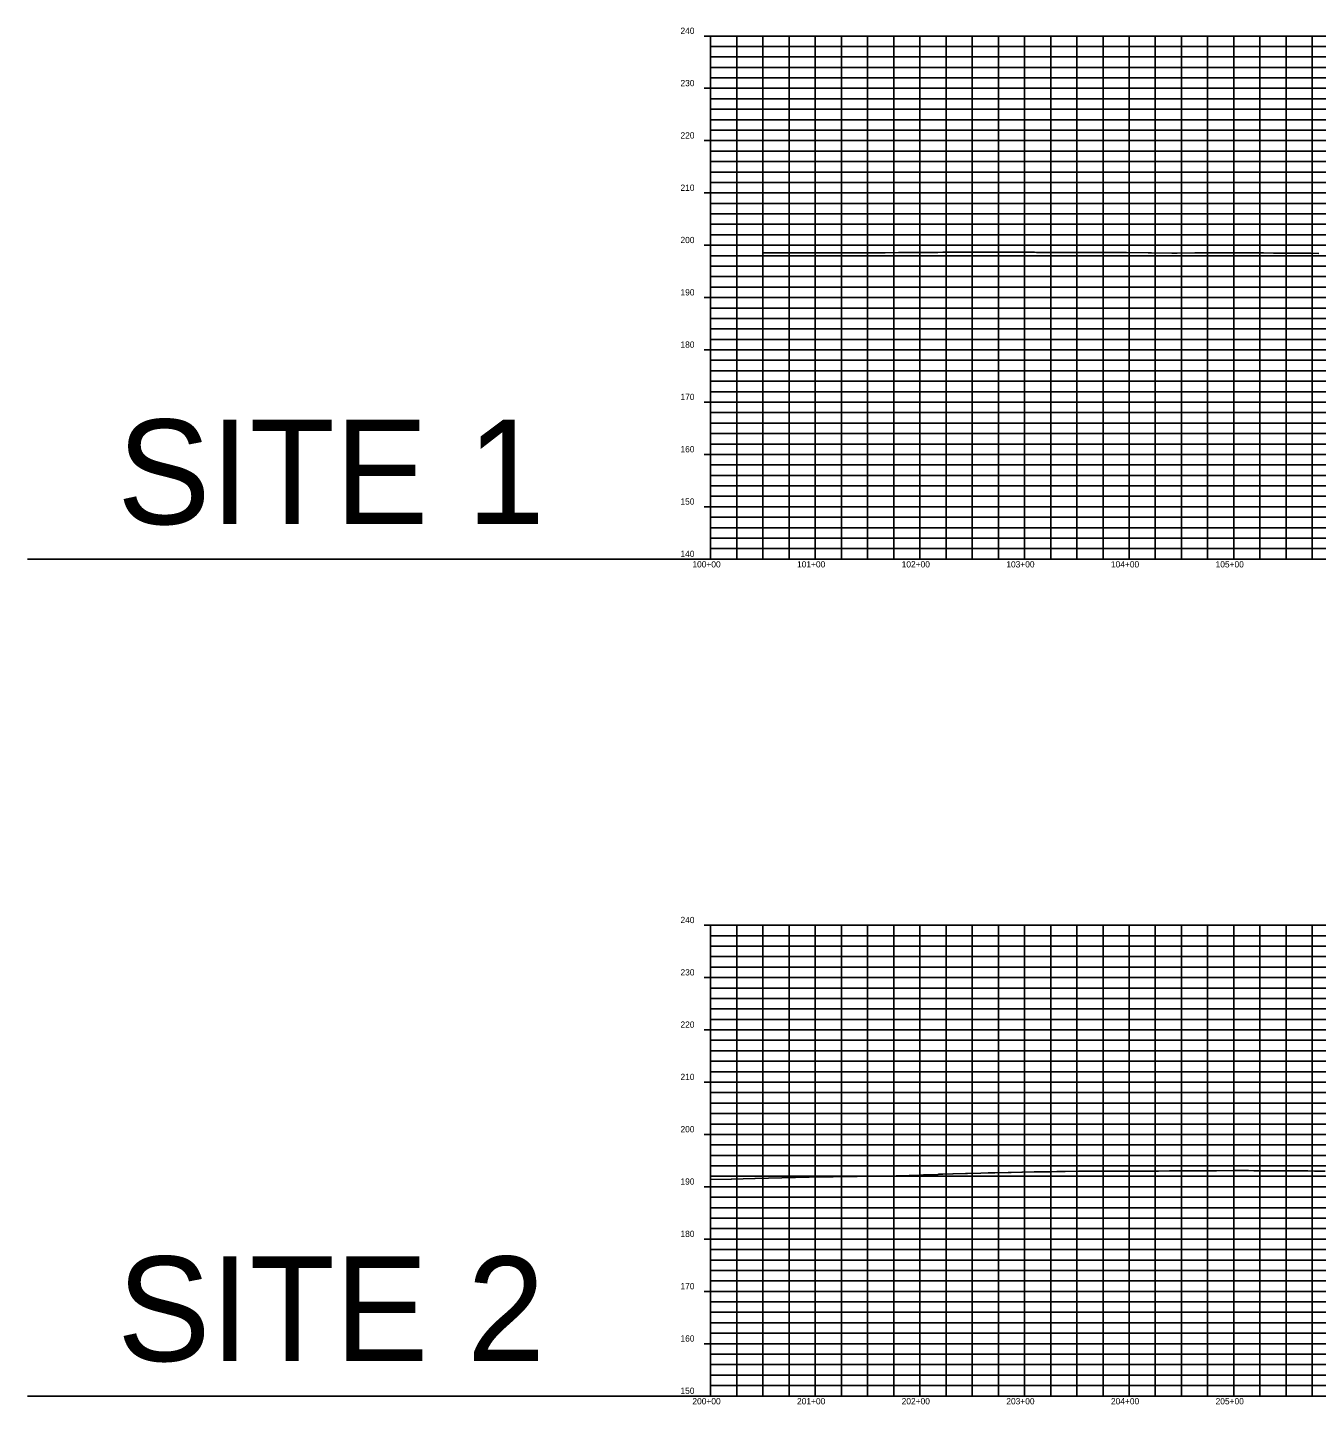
# Model space of a CAD drawing. Extents: x 1399671 to 1408349, y 1930471 to 1933387.
# Drawn here: x 1399671 to 1400903, y 1932071 to 1933387 of the extents above; entities that cross this region are included whole.
import ezdxf

# ---------------------------------------------------------------- set-up
doc = ezdxf.new("R2010")
doc.units = 0
for name, color, linetype in [('63', 7, 'Continuous'), ('8', 7, 'Continuous'), ('R_Exist Surface', 7, 'Continuous'), ('R_Grid', 7, 'Continuous'), ('R_Grid Annot', 7, 'Continuous')]:
    doc.layers.add(name, color=color, linetype=linetype)

msp = doc.modelspace()

# ---------------------------------------------------------------- linework, layer by layer
at = {"layer": '8'}
for p, q in [((1400324.2, 1932878.6), (1399671.4, 1932878.6)), ((1400324.2, 1932078.6), (1399671.4, 1932078.6))]:
    msp.add_line(p, q, dxfattribs=at)
at = {"layer": 'R_Exist Surface'}
for points in [[(1400374.2, 1933171.3), (1400384.1, 1933171.3), (1400384.1, 1933171.3), (1400388.6, 1933171.4), (1400397, 1933171.4), (1400397.1, 1933171.4), (1400414, 1933171.4), (1400414, 1933171.4), (1400414, 1933171.4), (1400431, 1933171.4), (1400431, 1933171.4), (1400447.9, 1933171.4), (1400447.9, 1933171.4), (1400464.9, 1933171.4), (1400464.9, 1933171.4), (1400477.9, 1933171.5), (1400477.9, 1933171.5), (1400480.9, 1933171.5), (1400490.9, 1933171.5), (1400490.9, 1933171.5), (1400503.9, 1933171.6), (1400503.9, 1933171.6), (1400516.9, 1933171.6), (1400524.2, 1933171.7), (1400541, 1933171.8), (1400541.3, 1933171.8), (1400546.1, 1933171.9), (1400565.4, 1933172), (1400565.6, 1933172), (1400568, 1933172), (1400578.5, 1933172), (1400578.5, 1933172), (1400584.6, 1933172), (1400589.9, 1933172), (1400591.3, 1933172), (1400591.4, 1933172), (1400591.4, 1933172), (1400604.3, 1933172), (1400604.4, 1933172), (1400611.7, 1933172), (1400617.1, 1933172), (1400617.6, 1933172), (1400633.6, 1933171.9), (1400635.7, 1933171.8), (1400653.6, 1933171.7), (1400654.3, 1933171.7), (1400655.5, 1933171.7), (1400669.7, 1933171.7), (1400670.6, 1933171.7), (1400677.4, 1933171.7), (1400685.7, 1933171.7), (1400686.8, 1933171.7), (1400699.3, 1933171.7), (1400701.6, 1933171.7), (1400703, 1933171.7), (1400704.3, 1933171.7), (1400719.2, 1933171.7), (1400721.2, 1933171.6), (1400721.6, 1933171.6), (1400742.4, 1933171.4), (1400743.1, 1933171.4), (1400745.6, 1933171.4), (1400765, 1933171.1), (1400765.7, 1933171.1), (1400770, 1933171.1), (1400786.9, 1933171.2), (1400790.2, 1933171.2), (1400795.6, 1933171.3), (1400808.7, 1933171.3), (1400814.8, 1933171.3), (1400826.2, 1933171.3), (1400830.6, 1933171.3), (1400830.6, 1933171.3), (1400835.3, 1933171.3), (1400846.4, 1933171.2), (1400851.6, 1933171.2), (1400852.5, 1933171.2), (1400862.2, 1933171.1), (1400868.1, 1933171.1), (1400874.4, 1933171.1), (1400878, 1933171.1), (1400883.6, 1933171), (1400891.7, 1933171), (1400896.3, 1933170.9), (1400897.9, 1933170.9), (1400905.4, 1933170.8)], [(1400324.2, 1932285.4), (1400343.9, 1932286), (1400344.1, 1932286), (1400366.4, 1932286.6), (1400366.7, 1932286.6), (1400379.4, 1932286.9), (1400379.6, 1932286.9), (1400392.3, 1932287.2), (1400392.4, 1932287.2), (1400405.2, 1932287.5), (1400405.3, 1932287.5), (1400418.2, 1932287.8), (1400418.2, 1932287.8), (1400418.3, 1932287.8), (1400441.1, 1932288.1), (1400441.3, 1932288.1), (1400463.9, 1932288.3), (1400464.1, 1932288.3), (1400476.5, 1932288.6), (1400476.7, 1932288.6), (1400489, 1932288.9), (1400489.3, 1932288.9), (1400501.6, 1932289.2), (1400513.9, 1932289.5), (1400514.2, 1932289.5), (1400524.2, 1932289.8), (1400527.6, 1932290), (1400528, 1932290), (1400541.4, 1932290.4), (1400541.8, 1932290.4), (1400542.1, 1932290.5), (1400546, 1932290.6), (1400555.6, 1932290.9), (1400555.9, 1932290.9), (1400567.8, 1932291.4), (1400569.4, 1932291.4), (1400569.7, 1932291.4), (1400582.5, 1932291.7), (1400589.6, 1932291.9), (1400595.4, 1932292), (1400595.7, 1932292), (1400608.7, 1932292.3), (1400608.8, 1932292.3), (1400611.4, 1932292.4), (1400621.9, 1932292.6), (1400621.9, 1932292.6), (1400622.2, 1932292.6), (1400633.3, 1932292.8), (1400635.6, 1932292.8), (1400635.7, 1932292.8), (1400649.2, 1932293), (1400655.1, 1932293.1), (1400662.3, 1932293.2), (1400662.9, 1932293.2), (1400675.8, 1932293.4), (1400676.6, 1932293.4), (1400676.9, 1932293.4), (1400698.5, 1932293.5), (1400698.7, 1932293.5), (1400700.6, 1932293.5), (1400702.8, 1932293.5), (1400720.5, 1932293.5), (1400724.6, 1932293.5), (1400726.3, 1932293.5), (1400737.3, 1932293.6), (1400739.2, 1932293.6), (1400742.3, 1932293.6), (1400750, 1932293.6), (1400752.2, 1932293.6), (1400762.8, 1932293.7), (1400764.1, 1932293.7), (1400772.9, 1932293.7), (1400775.5, 1932293.7), (1400786, 1932293.8), (1400794.3, 1932293.9), (1400800.2, 1932293.9), (1400806.6, 1932294), (1400807.8, 1932294), (1400824.7, 1932294.1), (1400829.1, 1932294.1), (1400829.6, 1932294.1), (1400838.3, 1932294.1), (1400843.2, 1932294), (1400851.4, 1932294), (1400851.8, 1932294), (1400859.9, 1932294), (1400865.4, 1932294), (1400873, 1932294), (1400873.2, 1932294), (1400879, 1932293.9), (1400890.6, 1932293.7), (1400895, 1932293.7), (1400901.4, 1932293.6), (1400911.5, 1932293.4)]]:
    msp.add_lwpolyline(points, dxfattribs=at)
at = {"layer": 'R_Grid'}
for p, q in [((1400324.2, 1932878.6), (1400324.2, 1933378.6)), ((1400324.2, 1933378.6), (1408224.2, 1933378.6)), ((1400324.2, 1933378.6), (1408224.2, 1933378.6)), ((1400324.2, 1933368.6), (1408224.2, 1933368.6)), ((1400349.2, 1932878.6), (1400349.2, 1933378.6)), ((1400374.2, 1932878.6), (1400374.2, 1933378.6)), ((1400399.2, 1932878.6), (1400399.2, 1933378.6)), ((1400424.2, 1932878.6), (1400424.2, 1933378.6)), ((1400449.2, 1932878.6), (1400449.2, 1933378.6)), ((1400474.2, 1932878.6), (1400474.2, 1933378.6)), ((1400499.2, 1932878.6), (1400499.2, 1933378.6)), ((1400524.2, 1932878.6), (1400524.2, 1933378.6)), ((1400549.2, 1932878.6), (1400549.2, 1933378.6)), ((1400574.2, 1932878.6), (1400574.2, 1933378.6)), ((1400599.2, 1932878.6), (1400599.2, 1933378.6)), ((1400624.2, 1932878.6), (1400624.2, 1933378.6)), ((1400649.2, 1932878.6), (1400649.2, 1933378.6)), ((1400674.2, 1932878.6), (1400674.2, 1933378.6)), ((1400699.2, 1932878.6), (1400699.2, 1933378.6)), ((1400724.2, 1932878.6), (1400724.2, 1933378.6)), ((1400749.2, 1932878.6), (1400749.2, 1933378.6)), ((1400774.2, 1932878.6), (1400774.2, 1933378.6)), ((1400799.2, 1932878.6), (1400799.2, 1933378.6)), ((1400824.2, 1932878.6), (1400824.2, 1933378.6)), ((1400849.2, 1932878.6), (1400849.2, 1933378.6)), ((1400874.2, 1932878.6), (1400874.2, 1933378.6)), ((1400899.2, 1932878.6), (1400899.2, 1933378.6)), ((1400324.2, 1933358.6), (1408224.2, 1933358.6)), ((1400324.2, 1933348.6), (1408224.2, 1933348.6)), ((1400324.2, 1933338.6), (1408224.2, 1933338.6)), ((1400324.2, 1933328.6), (1408224.2, 1933328.6)), ((1400324.2, 1933318.6), (1408224.2, 1933318.6)), ((1400324.2, 1933308.6), (1408224.2, 1933308.6)), ((1400324.2, 1933298.6), (1408224.2, 1933298.6)), ((1400324.2, 1933288.6), (1408224.2, 1933288.6)), ((1400324.2, 1933278.6), (1408224.2, 1933278.6)), ((1400324.2, 1933268.6), (1408224.2, 1933268.6)), ((1400324.2, 1933258.6), (1408224.2, 1933258.6)), ((1400324.2, 1933248.6), (1408224.2, 1933248.6)), ((1400324.2, 1933238.6), (1408224.2, 1933238.6)), ((1400324.2, 1933228.6), (1408224.2, 1933228.6)), ((1400324.2, 1933218.6), (1408224.2, 1933218.6)), ((1400324.2, 1933208.6), (1408224.2, 1933208.6)), ((1400324.2, 1933198.6), (1408224.2, 1933198.6)), ((1400324.2, 1933188.6), (1408224.2, 1933188.6)), ((1400324.2, 1933178.6), (1408224.2, 1933178.6)), ((1400324.2, 1933168.6), (1408224.2, 1933168.6)), ((1400324.2, 1933158.6), (1408224.2, 1933158.6)), ((1400324.2, 1933148.6), (1408224.2, 1933148.6)), ((1400324.2, 1933138.6), (1408224.2, 1933138.6)), ((1400324.2, 1933128.6), (1408224.2, 1933128.6)), ((1400324.2, 1933118.6), (1408224.2, 1933118.6)), ((1400324.2, 1933108.6), (1408224.2, 1933108.6)), ((1400324.2, 1933098.6), (1408224.2, 1933098.6)), ((1400324.2, 1933088.6), (1408224.2, 1933088.6)), ((1400324.2, 1933078.6), (1408224.2, 1933078.6)), ((1400324.2, 1933068.6), (1408224.2, 1933068.6)), ((1400324.2, 1933058.6), (1408224.2, 1933058.6)), ((1400324.2, 1933048.6), (1408224.2, 1933048.6)), ((1400324.2, 1933038.6), (1408224.2, 1933038.6)), ((1400324.2, 1933028.6), (1408224.2, 1933028.6)), ((1400324.2, 1933018.6), (1408224.2, 1933018.6)), ((1400324.2, 1933008.6), (1408224.2, 1933008.6)), ((1400324.2, 1932998.6), (1408224.2, 1932998.6)), ((1400324.2, 1932988.6), (1408224.2, 1932988.6)), ((1400324.2, 1932978.6), (1408224.2, 1932978.6)), ((1400324.2, 1932968.6), (1408224.2, 1932968.6)), ((1400324.2, 1932958.6), (1408224.2, 1932958.6)), ((1400324.2, 1932948.6), (1408224.2, 1932948.6)), ((1400324.2, 1932938.6), (1408224.2, 1932938.6)), ((1400324.2, 1932928.6), (1408224.2, 1932928.6)), ((1400324.2, 1932918.6), (1408224.2, 1932918.6)), ((1400324.2, 1932908.6), (1408224.2, 1932908.6)), ((1400324.2, 1932898.6), (1408224.2, 1932898.6)), ((1400324.2, 1932888.6), (1408224.2, 1932888.6)), ((1400324.2, 1932878.6), (1408224.2, 1932878.6)), ((1400324.2, 1932078.6), (1400324.2, 1932528.6)), ((1400324.2, 1932528.6), (1407124.2, 1932528.6)), ((1400324.2, 1932528.6), (1407124.2, 1932528.6)), ((1400349.2, 1932078.6), (1400349.2, 1932528.6)), ((1400374.2, 1932078.6), (1400374.2, 1932528.6)), ((1400399.2, 1932078.6), (1400399.2, 1932528.6)), ((1400424.2, 1932078.6), (1400424.2, 1932528.6)), ((1400449.2, 1932078.6), (1400449.2, 1932528.6)), ((1400474.2, 1932078.6), (1400474.2, 1932528.6)), ((1400499.2, 1932078.6), (1400499.2, 1932528.6)), ((1400524.2, 1932078.6), (1400524.2, 1932528.6)), ((1400549.2, 1932078.6), (1400549.2, 1932528.6)), ((1400574.2, 1932078.6), (1400574.2, 1932528.6)), ((1400599.2, 1932078.6), (1400599.2, 1932528.6)), ((1400624.2, 1932078.6), (1400624.2, 1932528.6)), ((1400649.2, 1932078.6), (1400649.2, 1932528.6)), ((1400674.2, 1932078.6), (1400674.2, 1932528.6)), ((1400699.2, 1932078.6), (1400699.2, 1932528.6)), ((1400724.2, 1932078.6), (1400724.2, 1932528.6)), ((1400749.2, 1932078.6), (1400749.2, 1932528.6)), ((1400774.2, 1932078.6), (1400774.2, 1932528.6)), ((1400799.2, 1932078.6), (1400799.2, 1932528.6)), ((1400824.2, 1932078.6), (1400824.2, 1932528.6)), ((1400849.2, 1932078.6), (1400849.2, 1932528.6)), ((1400874.2, 1932078.6), (1400874.2, 1932528.6)), ((1400899.2, 1932078.6), (1400899.2, 1932528.6)), ((1400324.2, 1932518.6), (1407124.2, 1932518.6)), ((1400324.2, 1932508.6), (1407124.2, 1932508.6)), ((1400324.2, 1932498.6), (1407124.2, 1932498.6)), ((1400324.2, 1932488.6), (1407124.2, 1932488.6)), ((1400324.2, 1932478.6), (1407124.2, 1932478.6)), ((1400324.2, 1932468.6), (1407124.2, 1932468.6)), ((1400324.2, 1932458.6), (1407124.2, 1932458.6)), ((1400324.2, 1932448.6), (1407124.2, 1932448.6)), ((1400324.2, 1932438.6), (1407124.2, 1932438.6)), ((1400324.2, 1932428.6), (1407124.2, 1932428.6)), ((1400324.2, 1932418.6), (1407124.2, 1932418.6)), ((1400324.2, 1932408.6), (1407124.2, 1932408.6)), ((1400324.2, 1932398.6), (1407124.2, 1932398.6)), ((1400324.2, 1932388.6), (1407124.2, 1932388.6)), ((1400324.2, 1932378.6), (1407124.2, 1932378.6)), ((1400324.2, 1932368.6), (1407124.2, 1932368.6)), ((1400324.2, 1932358.6), (1407124.2, 1932358.6)), ((1400324.2, 1932348.6), (1407124.2, 1932348.6)), ((1400324.2, 1932338.6), (1407124.2, 1932338.6)), ((1400324.2, 1932328.6), (1407124.2, 1932328.6)), ((1400324.2, 1932318.6), (1407124.2, 1932318.6)), ((1400324.2, 1932308.6), (1407124.2, 1932308.6)), ((1400324.2, 1932298.6), (1407124.2, 1932298.6)), ((1400324.2, 1932288.6), (1407124.2, 1932288.6)), ((1400324.2, 1932278.6), (1407124.2, 1932278.6)), ((1400324.2, 1932268.6), (1407124.2, 1932268.6)), ((1400324.2, 1932258.6), (1407124.2, 1932258.6)), ((1400324.2, 1932248.6), (1407124.2, 1932248.6)), ((1400324.2, 1932238.6), (1407124.2, 1932238.6)), ((1400324.2, 1932228.6), (1407124.2, 1932228.6)), ((1400324.2, 1932218.6), (1407124.2, 1932218.6)), ((1400324.2, 1932208.6), (1407124.2, 1932208.6)), ((1400324.2, 1932198.6), (1407124.2, 1932198.6)), ((1400324.2, 1932188.6), (1407124.2, 1932188.6)), ((1400324.2, 1932178.6), (1407124.2, 1932178.6)), ((1400324.2, 1932168.6), (1407124.2, 1932168.6)), ((1400324.2, 1932158.6), (1407124.2, 1932158.6)), ((1400324.2, 1932148.6), (1407124.2, 1932148.6)), ((1400324.2, 1932138.6), (1407124.2, 1932138.6)), ((1400324.2, 1932128.6), (1407124.2, 1932128.6)), ((1400324.2, 1932118.6), (1407124.2, 1932118.6)), ((1400324.2, 1932108.6), (1407124.2, 1932108.6)), ((1400324.2, 1932098.6), (1407124.2, 1932098.6)), ((1400324.2, 1932088.6), (1407124.2, 1932088.6)), ((1400324.2, 1932078.6), (1407124.2, 1932078.6))]:
    msp.add_line(p, q, dxfattribs=at)
at = {"layer": 'R_Grid Annot'}
for p, q in [((1400318.2, 1933378.6), (1400324.2, 1933378.6)), ((1400318.2, 1933378.6), (1400324.2, 1933378.6)), ((1400324.2, 1933368.6), (1400327.2, 1933368.6)), ((1400324.2, 1933358.6), (1400327.2, 1933358.6)), ((1400324.2, 1933348.6), (1400327.2, 1933348.6)), ((1400324.2, 1933338.6), (1400327.2, 1933338.6)), ((1400318.2, 1933328.6), (1400324.2, 1933328.6)), ((1400324.2, 1933318.6), (1400327.2, 1933318.6)), ((1400324.2, 1933308.6), (1400327.2, 1933308.6)), ((1400324.2, 1933298.6), (1400327.2, 1933298.6)), ((1400318.2, 1933278.6), (1400324.2, 1933278.6)), ((1400324.2, 1933288.6), (1400327.2, 1933288.6)), ((1400324.2, 1933268.6), (1400327.2, 1933268.6)), ((1400324.2, 1933258.6), (1400327.2, 1933258.6)), ((1400324.2, 1933248.6), (1400327.2, 1933248.6)), ((1400324.2, 1933238.6), (1400327.2, 1933238.6)), ((1400318.2, 1933228.6), (1400324.2, 1933228.6)), ((1400324.2, 1933218.6), (1400327.2, 1933218.6)), ((1400324.2, 1933208.6), (1400327.2, 1933208.6)), ((1400324.2, 1933198.6), (1400327.2, 1933198.6)), ((1400324.2, 1933188.6), (1400327.2, 1933188.6)), ((1400318.2, 1933178.6), (1400324.2, 1933178.6)), ((1400324.2, 1933168.6), (1400327.2, 1933168.6)), ((1400324.2, 1933158.6), (1400327.2, 1933158.6)), ((1400324.2, 1933148.6), (1400327.2, 1933148.6)), ((1400324.2, 1933138.6), (1400327.2, 1933138.6)), ((1400318.2, 1933128.6), (1400324.2, 1933128.6)), ((1400324.2, 1933118.6), (1400327.2, 1933118.6)), ((1400324.2, 1933108.6), (1400327.2, 1933108.6)), ((1400324.2, 1933098.6), (1400327.2, 1933098.6)), ((1400324.2, 1933088.6), (1400327.2, 1933088.6)), ((1400318.2, 1933078.6), (1400324.2, 1933078.6)), ((1400324.2, 1933068.6), (1400327.2, 1933068.6)), ((1400324.2, 1933058.6), (1400327.2, 1933058.6)), ((1400324.2, 1933048.6), (1400327.2, 1933048.6)), ((1400318.2, 1933028.6), (1400324.2, 1933028.6)), ((1400324.2, 1933038.6), (1400327.2, 1933038.6)), ((1400324.2, 1933018.6), (1400327.2, 1933018.6)), ((1400324.2, 1933008.6), (1400327.2, 1933008.6)), ((1400324.2, 1932998.6), (1400327.2, 1932998.6)), ((1400324.2, 1932988.6), (1400327.2, 1932988.6)), ((1400318.2, 1932978.6), (1400324.2, 1932978.6)), ((1400324.2, 1932968.6), (1400327.2, 1932968.6)), ((1400324.2, 1932958.6), (1400327.2, 1932958.6)), ((1400324.2, 1932948.6), (1400327.2, 1932948.6)), ((1400324.2, 1932938.6), (1400327.2, 1932938.6)), ((1400318.2, 1932928.6), (1400324.2, 1932928.6)), ((1400324.2, 1932918.6), (1400327.2, 1932918.6)), ((1400324.2, 1932908.6), (1400327.2, 1932908.6)), ((1400324.2, 1932898.6), (1400327.2, 1932898.6)), ((1400324.2, 1932888.6), (1400327.2, 1932888.6)), ((1400318.2, 1932878.6), (1400324.2, 1932878.6)), ((1400318.2, 1932528.6), (1400324.2, 1932528.6)), ((1400318.2, 1932528.6), (1400324.2, 1932528.6)), ((1400324.2, 1932518.6), (1400327.2, 1932518.6)), ((1400324.2, 1932508.6), (1400327.2, 1932508.6)), ((1400324.2, 1932498.6), (1400327.2, 1932498.6)), ((1400324.2, 1932488.6), (1400327.2, 1932488.6)), ((1400318.2, 1932478.6), (1400324.2, 1932478.6)), ((1400324.2, 1932468.6), (1400327.2, 1932468.6)), ((1400324.2, 1932458.6), (1400327.2, 1932458.6)), ((1400324.2, 1932448.6), (1400327.2, 1932448.6)), ((1400324.2, 1932438.6), (1400327.2, 1932438.6)), ((1400318.2, 1932428.6), (1400324.2, 1932428.6)), ((1400324.2, 1932418.6), (1400327.2, 1932418.6)), ((1400324.2, 1932408.6), (1400327.2, 1932408.6)), ((1400324.2, 1932398.6), (1400327.2, 1932398.6)), ((1400324.2, 1932388.6), (1400327.2, 1932388.6)), ((1400318.2, 1932378.6), (1400324.2, 1932378.6)), ((1400324.2, 1932368.6), (1400327.2, 1932368.6)), ((1400324.2, 1932358.6), (1400327.2, 1932358.6)), ((1400324.2, 1932348.6), (1400327.2, 1932348.6)), ((1400318.2, 1932328.6), (1400324.2, 1932328.6)), ((1400324.2, 1932338.6), (1400327.2, 1932338.6)), ((1400324.2, 1932318.6), (1400327.2, 1932318.6)), ((1400324.2, 1932308.6), (1400327.2, 1932308.6)), ((1400324.2, 1932298.6), (1400327.2, 1932298.6)), ((1400318.2, 1932278.6), (1400324.2, 1932278.6)), ((1400324.2, 1932288.6), (1400327.2, 1932288.6)), ((1400324.2, 1932268.6), (1400327.2, 1932268.6)), ((1400324.2, 1932258.6), (1400327.2, 1932258.6)), ((1400324.2, 1932248.6), (1400327.2, 1932248.6)), ((1400324.2, 1932238.6), (1400327.2, 1932238.6)), ((1400318.2, 1932228.6), (1400324.2, 1932228.6)), ((1400324.2, 1932218.6), (1400327.2, 1932218.6)), ((1400324.2, 1932208.6), (1400327.2, 1932208.6)), ((1400324.2, 1932198.6), (1400327.2, 1932198.6)), ((1400324.2, 1932188.6), (1400327.2, 1932188.6)), ((1400318.2, 1932178.6), (1400324.2, 1932178.6)), ((1400324.2, 1932168.6), (1400327.2, 1932168.6)), ((1400324.2, 1932158.6), (1400327.2, 1932158.6)), ((1400324.2, 1932148.6), (1400327.2, 1932148.6)), ((1400324.2, 1932138.6), (1400327.2, 1932138.6)), ((1400318.2, 1932128.6), (1400324.2, 1932128.6)), ((1400324.2, 1932118.6), (1400327.2, 1932118.6)), ((1400324.2, 1932108.6), (1400327.2, 1932108.6)), ((1400324.2, 1932098.6), (1400327.2, 1932098.6)), ((1400318.2, 1932078.6), (1400324.2, 1932078.6)), ((1400324.2, 1932088.6), (1400327.2, 1932088.6))]:
    msp.add_line(p, q, dxfattribs=at)

# ---------------------------------------------------------------- texts
at = {"layer": '63'}
for p in [(1400324.2, 1932878.6), (1400324.2, 1932078.6)]:
    msp.add_text('-', height=0.0001, dxfattribs=at).set_placement(p)
at = {"layer": '8'}
for s, p in [('SITE 1', (1399757.1, 1932912)), ('SITE 2', (1399757.1, 1932112))]:
    msp.add_text(s, height=100, dxfattribs=at).set_placement(p)
at = {"layer": 'R_Grid Annot'}
for s, p in [('240', (1400295.4, 1933380.6)), ('240', (1400295.4, 1933380.6)), ('230', (1400295.4, 1933330.6)), ('220', (1400295.4, 1933280.6)), ('210', (1400295.4, 1933230.6)), ('200', (1400295.4, 1933180.6)), ('190', (1400295.4, 1933130.6)), ('180', (1400295.4, 1933080.6)), ('170', (1400295.4, 1933030.6)), ('160', (1400295.4, 1932980.6)), ('150', (1400295.4, 1932930.6)), ('140', (1400295.4, 1932880.6)), ('100+00', (1400306.8, 1932870.6)), ('101+00', (1400406.8, 1932870.6)), ('102+00', (1400506.8, 1932870.6)), ('103+00', (1400606.8, 1932870.6)), ('104+00', (1400706.8, 1932870.6)), ('105+00', (1400806.8, 1932870.6)), ('240', (1400295.4, 1932530.6)), ('240', (1400295.4, 1932530.6)), ('230', (1400295.4, 1932480.6)), ('220', (1400295.4, 1932430.6)), ('210', (1400295.4, 1932380.6)), ('200', (1400295.4, 1932330.6)), ('190', (1400295.4, 1932280.6)), ('180', (1400295.4, 1932230.6)), ('170', (1400295.4, 1932180.6)), ('160', (1400295.4, 1932130.6)), ('150', (1400295.4, 1932080.6)), ('200+00', (1400306.8, 1932070.6)), ('201+00', (1400406.8, 1932070.6)), ('202+00', (1400506.8, 1932070.6)), ('203+00', (1400606.8, 1932070.6)), ('204+00', (1400706.8, 1932070.6)), ('205+00', (1400806.8, 1932070.6))]:
    msp.add_text(s, height=6, dxfattribs=at).set_placement(p)

doc.saveas('drawing.dxf')
